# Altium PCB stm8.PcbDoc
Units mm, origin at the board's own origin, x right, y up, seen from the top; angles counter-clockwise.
Board outline 26 x 52.96 mm, 2 copper layers (Top Layer, Bottom Layer); 15 components, 22 nets, 75 pads, 10 vias.
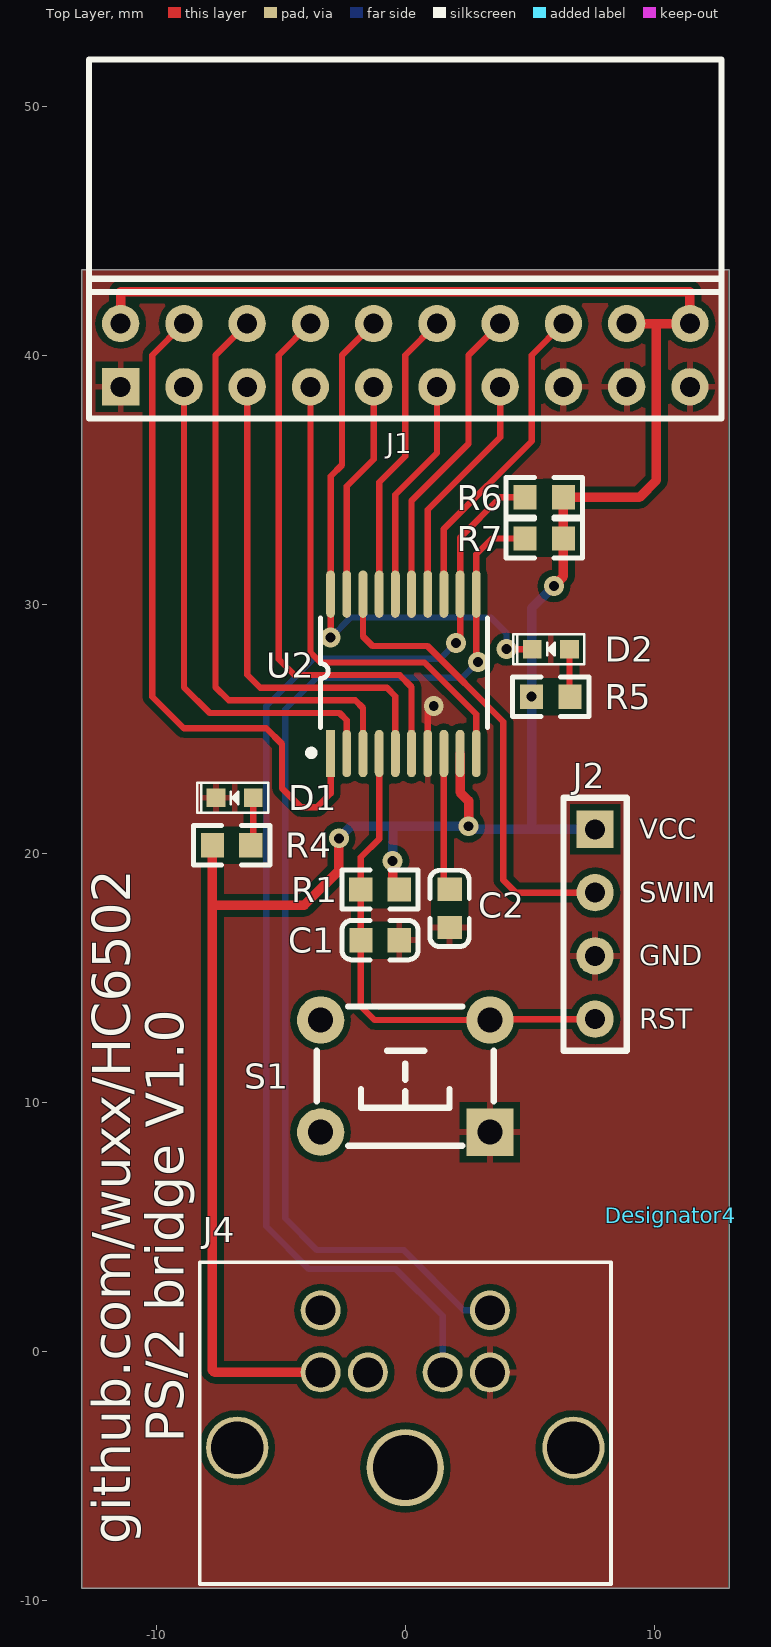
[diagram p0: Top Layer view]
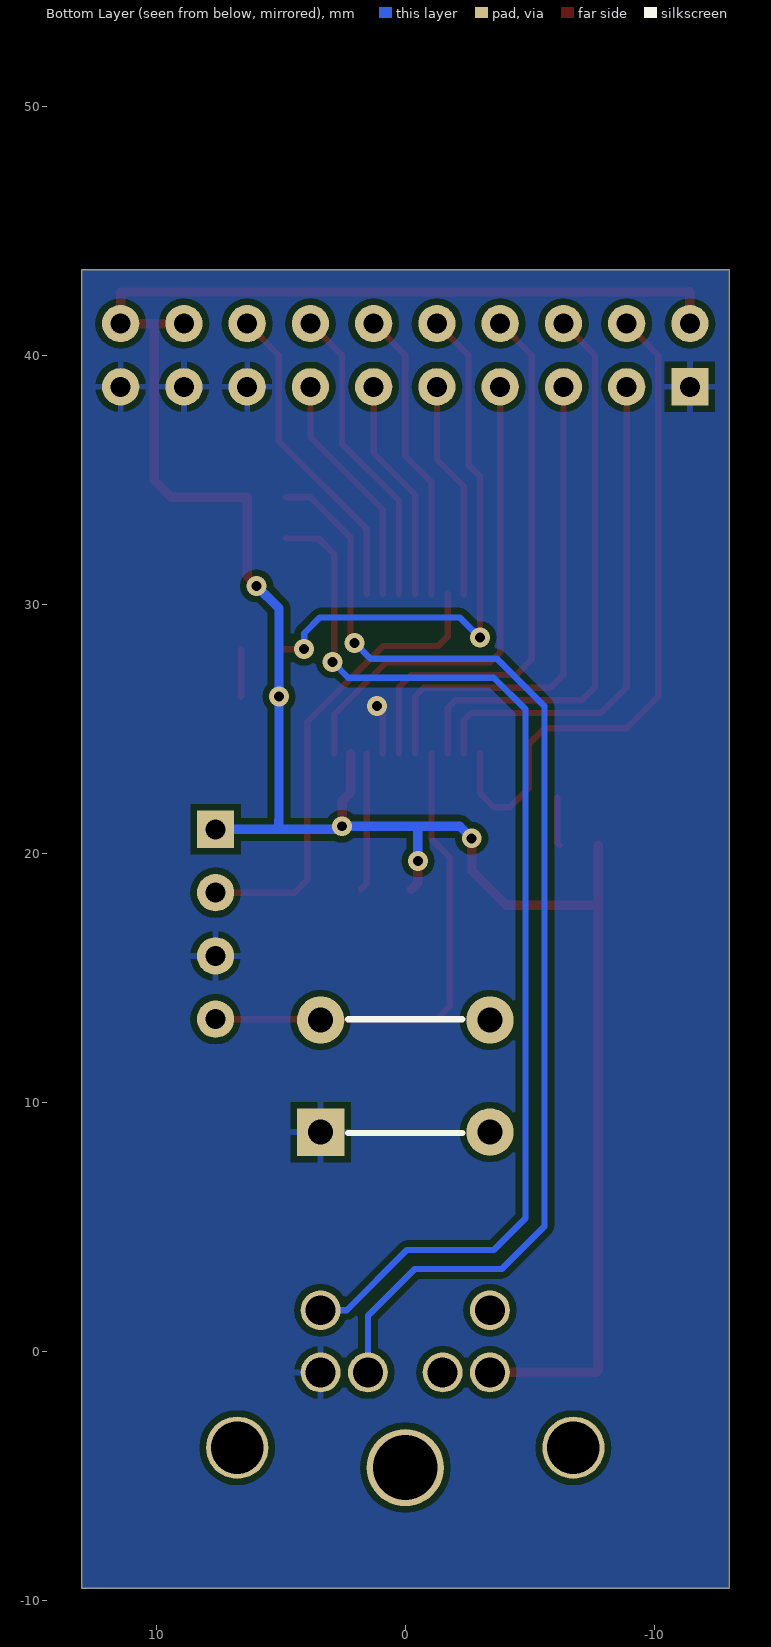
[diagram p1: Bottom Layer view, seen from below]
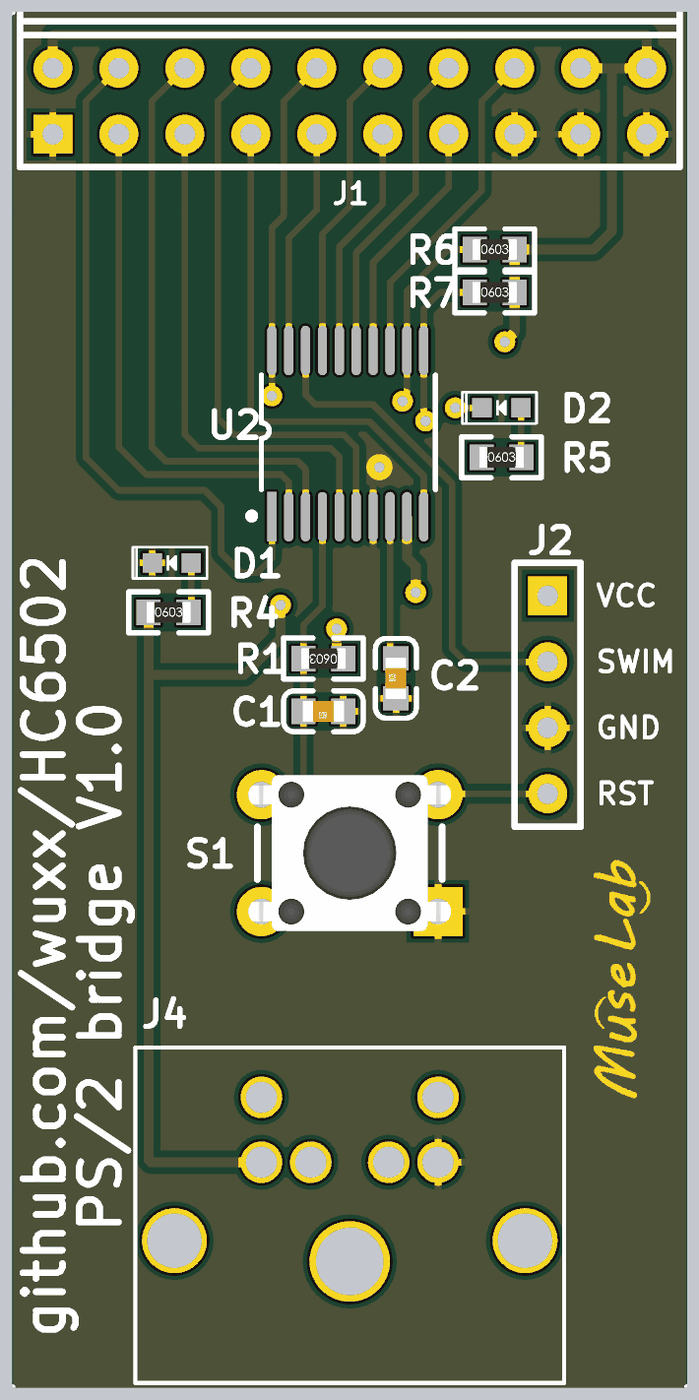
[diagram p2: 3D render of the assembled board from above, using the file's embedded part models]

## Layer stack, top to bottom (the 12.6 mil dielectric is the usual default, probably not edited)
Top Solder: solder mask 0.0102, Solder Resist, Dk 3.5
Top Layer: signal copper 0.0356
Dielectric 1: dielectric 0.32, FR-4, Dk 4.8
Bottom Layer: signal copper 0.0356
Bottom Solder: solder mask 0.0102, Solder Resist, Dk 3.5

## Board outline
-13,-9.525 -13,43.434 13,43.434 13,-9.525

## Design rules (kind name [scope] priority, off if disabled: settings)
Clearance [All] p1: gap=0.254 ignorepadtopadclearanceinfootprint=FALSE except(0: Arc-Hole Track-Hole SMDPad-Hole THPad-Hole Via-Hole Fill-Hole Poly-Hole Region-Hole Text-Hole)
DiffPairsRouting [All] p1: maxlimit=0.254 minlimit=0.254 mostfreqgap=0.254 toplayer_minwidth=0.152 toplayer_maxwidth=0.381 toplayer_prefwidth=0.381 bottomlayer_minwidth=0.152 bottomlayer_maxwidth=0.381 bottomlayer_prefwidth=0.381 maxuncoupledlength=12.7
PolygonConnect [All] p1: thpad.connectstyle=Relief thpad.reliefconductorwidth=0.254 thpad.reliefentries=4 thpad.polygonreliefangle="90 Angle" thpad.airgapwidth=0.254 smdpad.connectstyle=Relief smdpad.reliefconductorwidth=0.254 smdpad.reliefentries=4 smdpad.polygonreliefangle="90 Angle" smdpad.airgapwidth=0.254 via.connectstyle=Direct via.reliefconductorwidth=0.254 via.reliefentries=4 via.polygonreliefangle="90 Angle" via.airgapwidth=0.254
RoutingVias [All] p1: holewidth=0.4 width=0.8 viastyle="Through Hole" minholewidth=0.4 minwidth=0.8 maxholewidth=0.4 maxwidth=0.8
SolderMaskExpansion [All] p1: expansion=0.102
Width [All] p1: maxlimit=2.54 minlimit=0.152 preferedwidth=0.254
29 further rules are at their usual default settings.

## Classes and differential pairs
component class stm8: C1 C2 D1 D2 J1 J2 J4 R1 R4 R5 R6 R7 S1 U2

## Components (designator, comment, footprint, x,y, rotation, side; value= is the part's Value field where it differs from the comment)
C1 "Cap" 0603_C -0.254,16.51 r180 top value=100nF
C2 "Cap" 0603_C 1.778,17.018 r90 top value=1uF
D1 "LED0" 0603_LED -6.85,22.225 r180 top
D2 "LED0" 0603_LED 5.842,28.194 r180 top
Designator4 "Comment" LOGO 10.668,5.461 r90 top
J1 "IDC20" IDC20 0,40 r0 top
J2 "Header 4" HEADER_4x1 7.62,20.955 r270 top
J4 "PS2" PS2 0,-0.873 r180 top
R1 "Res2" 0603_R -0.254,18.542 r180 top value=1K
R4 "Res2" 0603_R -7.739,20.32 r0 top value=1K
R5 "Res2" 0603_R 5.08,26.289 r0 top value=1K
R6 "Res2" 0603_R 4.818,34.29 r0 top value=4.7K
R7 "Res2" 0603_R 4.818,32.639 r0 top value=4.7K
S1 "SW-PB" "TSW DIP-6*6*6" 0,11.049 r180 top
U2 "STM8S103F3P6" TSSOP20 -3,24.003 r90 top locked

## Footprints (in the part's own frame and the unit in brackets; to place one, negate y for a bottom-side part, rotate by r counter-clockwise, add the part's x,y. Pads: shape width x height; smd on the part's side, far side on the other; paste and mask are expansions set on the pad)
0603_C [mm]
  rect 0.93x0.98 smd: 1(-0.008,0) 2(1.532,0)
  silkscreen extent -0.77,-0.79 2.3,0.79, body extent -0.04,-0.4 1.56,0.4, height 0.3
0603_LED [mm]
  rect 0.75x0.75 smd: 1(-0.75,0) 2(0.75,0)
  silkscreen extent -1.35,-0.6 1.5,0.6
0603_R [mm]
  rect 0.93x0.98 smd: 1(-0.008,0) 2(1.532,0)
  silkscreen extent -0.77,-0.79 2.3,0.79, body extent -0.09,-0.4 1.61,0.4, height 0.56
HEADER_4x1 [mm]
  rect 1.5x1.5 hole 0.8: 1(0,0)
  round 1.5 hole 0.8: 2(2.54,0) 3(5.08,0) 4(7.62,0)
  silkscreen extent -1.27,-1.27 8.89,1.27
IDC20 [mm]
  rect 1.5x1.5 hole 0.8: 1(-11.43,-1.27)
  round 1.5 hole 0.8: 2(-11.43,1.27) 3(-8.89,-1.27) 4(-8.89,1.27) 5(-6.35,-1.27) 6(-6.35,1.27) 7(-3.81,-1.27) 8(-3.81,1.27) 9(-1.27,-1.27) 10(-1.27,1.27) 11(1.27,-1.27) 12(1.27,1.27) 13(3.81,-1.27) 14(3.81,1.27) 15(6.35,-1.27) 16(6.35,1.27) 17(8.89,-1.27) 18(8.89,1.27) 19(11.43,-1.27) 20(11.43,1.27)
  silkscreen extent -12.7,-2.54 12.7,11.87
LOGO [mm]
PS2 [mm]
  round 1.6 hole 1.2: 1(-1.5,-0.02) 2(1.5,-0.02) 3(-3.4,-0.02) 4(3.4,-0.02) 5(-3.4,-2.52) 6(3.4,-2.52)
  round 2.5 hole 2.1: 7(-6.75,3) 9(6.75,3)
  round 3.1 hole 2.6: 8(0,3.8)
  silkscreen extent -8.26,-4.44 8.25,8.48
TSSOP20 [mm] "20-pin, 4.40 mm body, 0.65 mm pitch"
  rect 1.9x0.356 smd: 1(0,0)
  oval 1.9x0.356 smd: 2(0,-0.65) 3(0,-1.3) 4(0,-1.95) 5(0,-2.6) 6(0,-3.25) 7(0,-3.9) 8(0,-4.55) 9(0,-5.2) 10(0,-5.85) 11(6.4,-5.85) 12(6.4,-5.2) 13(6.4,-4.55) 14(6.4,-3.9) 15(6.4,-3.25) 16(6.4,-2.6) 17(6.4,-1.95) 18(6.4,-1.3) 19(6.4,-0.65) 20(6.4,0)
  silkscreen extent -0.1,-6.3 5.45,0.9
"TSW DIP-6*6*6" [mm] "6*6*6mm"
  rect 1.9x1.9 hole 1: 1(-3.4,2.25)
  round 1.9 hole 1: 2(-3.4,-2.25) 3(3.4,-2.25) 4(3.4,2.25)
  silkscreen extent -3.56,-2.79 3.56,2.79, body extent -4.11,-3 4.11,3, height 5.95

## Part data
C1 C2: "Capacitor"
D1 D2: "Typical INFRARED GaAs LED"
J2: "Header, 4-Pin"
R1 R4 R5 R6 R7: "Resistor"
S1: "Switch"
U2: "ST 8-bit  Microcontroller"

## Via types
v1: diameter 0.8, hole 0.4, Top Layer to Bottom Layer, 10 vias

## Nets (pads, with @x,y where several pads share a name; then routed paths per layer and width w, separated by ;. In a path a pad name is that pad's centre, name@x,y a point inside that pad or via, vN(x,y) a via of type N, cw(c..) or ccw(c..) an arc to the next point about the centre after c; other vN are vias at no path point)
5V: J1.2 J1.18 J1.20 J2.1 J4.4 R1.1 R4.1 R5.1 R6.2 R7.2 U2.9 | length 100.9
  Top Layer w0.254: R5.1@5.072,26.17 v1(5.072,26.289)
  Top Layer w0.381: J1.2 -11.43,42.545 11.43,42.545 J1.20 10.033,41.27 ; R4.1 -7.747,17.907 ; J4.4 -7.656,-0.853 -7.747,-0.762 -7.747,17.907 ; v1(-2.667,20.599) -2.667,19.304 -4.064,17.907 -7.747,17.907 ; v1(-0.508,19.685) -0.508,18.804 R1.1 ; U2.9 2.2,22.438 2.54,22.098 v1(2.54,21.082) ; v1(5.969,30.734) 6.35,31.115 R7.2 R6.2 9.398,34.29 10.085,34.977 10.085,41.218 10.033,41.27 ; J1.18 10.033,41.27
  Bottom Layer w0.381: v1(-2.667,20.599) -2.184,21.082 -0.508,21.082 ; v1(-0.508,19.685) -0.508,21.082 ; v1(5.969,30.734) 5.072,29.837 v1(5.072,26.289) 5.072,21.328 5.08,21.32 5.08,20.955 ; J2.1 5.08,20.955 ; -0.508,21.082 v1(2.54,21.082) 2.667,20.955 5.08,20.955
GND: C1.1 C2.1 D1.2 J1.1 J1.15 J1.17 J1.19 J2.3 J4.3 S1.1 U2.7 | length 2
  Top Layer w0.254: U2.7 0.9,25.665 v1(1.143,25.908)
NetC2_2: C2.2 U2.8 | length 5.5
  Top Layer w0.254: U2.8 1.55,18.778 C2.2
NetD1_1: D1.1 R4.2 | length 1.9
  Top Layer w0.254: R4.2 -6.1,20.427 D1.1
NetD2_1: D2.1 R5.2 | length 1.9
  Top Layer w0.254: D2.1 6.592,26.309 R5.2
NRST: C1.2 J2.4 R1.2 S1.2 U2.4 | length 20.1
  Top Layer w0.254: U2.4 -1.05,20.572 -1.786,19.836 R1.2 -1.786,17.501 C1.2 -1.786,13.851 -1.234,13.299 S1.2 3.436,13.335 J2.4
PA1: J1.5 U2.5 | length 20.2
  Top Layer w0.254: J1.5 -6.35,27.164 -5.831,26.645 -0.737,26.645 -0.4,26.308 U2.5
PA2: J1.8 U2.6 | length 22.5
  Top Layer w0.254: J1.8 -5.08,40 -5.08,27.788 -4.445,27.153 -0.229,27.153 0.25,26.674 U2.6
PA3: J1.7 U2.10 | length 19.9
  Top Layer w0.254: J1.7 -3.81,28.067 -3.404,27.661 0.767,27.661 2.85,25.578 U2.10
PB4: J4.1 R6.1 U2.12 | length 48
  Top Layer w0.254: v1(2.032,28.448) 2.2,28.616 U2.12 2.2,32.68 3.81,34.29 R6.1
  Bottom Layer w0.254: J4.1 1.5,1.421 -0.381,3.302 -3.872,3.302 -5.588,5.018 -5.588,25.908 -3.683,27.813 1.397,27.813 v1(2.032,28.448)
PB5: J4.5 R7.1 U2.11 | length 45.3
  Top Layer w0.254: v1(2.921,27.686) 2.85,27.757 U2.11 2.85,32.004 3.485,32.639 R7.1
  Bottom Layer w0.254: v1(2.921,27.686) 2.286,27.051 -3.556,27.051 -4.826,25.781 -4.826,5.334 -3.556,4.064 -0.065,4.064 2.352,1.647 J4.5
PC3: J1.16 U2.13 | length 12.9
  Top Layer w0.254: U2.13 1.55,33.02 5.08,36.55 5.08,40 J1.16
PC4: J1.13 U2.14 | length 9.5
  Top Layer w0.254: U2.14 0.9,33.793 3.81,36.703 J1.13
PC5: J1.14 U2.15 | length 12.3
  Top Layer w0.254: U2.15 0.25,34.159 2.54,36.449 2.54,40 J1.14
PC6: J1.11 U2.16 | length 9
  Top Layer w0.254: U2.16 -0.4,34.398 1.27,36.068 J1.11
PC7: J1.12 U2.17 | length 11.8
  Top Layer w0.254: U2.17 -1.05,34.891 0,35.941 0,40 J1.12
PD1: J2.2 U2.18 | length 19
  Top Layer w0.254: U2.18 -1.7,28.702 -1.319,28.321 0.889,28.321 3.937,25.273 3.937,18.923 4.445,18.415 J2.2
PD2: J1.9 U2.19 | length 8.8
  Top Layer w0.254: U2.19 -2.35,34.734 -1.27,35.814 J1.9
PD3: D2.2 J1.10 U2.20 | length 22.7
  Top Layer w0.254: v1(-3,28.654) U2.20 -3,35.131 -2.54,35.591 -2.54,40 J1.10 ; v1(4.064,28.194) D2.2
  Bottom Layer w0.254: v1(-3,28.654) -2.19,29.464 3.429,29.464 4.064,28.829 v1(4.064,28.194)
PD4: J1.4 U2.1 | length 27.4
  Top Layer w0.254: J1.4 -10.16,40 -10.16,26.289 -8.89,25.019 -5.588,25.019 -4.953,24.384 -4.953,22.606 -4.191,21.844 -3.556,21.844 -3,22.4 U2.1
PD5: J1.3 U2.2 | length 20.5
  Top Layer w0.254: J1.3 -8.89,26.67 -7.849,25.629 -2.642,25.629 -2.35,25.337 U2.2
PD6: J1.6 U2.3 | length 23.2
  Top Layer w0.254: J1.6 -7.62,40 -7.62,26.67 -7.087,26.137 -2.007,26.137 -1.7,25.83 U2.3
pads on no net: J4.2 J4.6 J4.7 J4.8 J4.9 S1.3 S1.4

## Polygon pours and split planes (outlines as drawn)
GND on Top Layer "GND_L01_P004" (solid, remove dead copper, pour order 4): -12.954,-9.525 12.954,-9.525 12.954,43.434 -12.954,43.434
GND on Bottom Layer "GND_L02_P006" (solid, remove dead copper, pour order 6): -12.954,-9.525 12.954,-9.525 12.954,43.434 -12.954,43.434

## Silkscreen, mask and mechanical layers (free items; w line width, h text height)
Top Overlay:
  text "VCC" at 9.398,20.574 h0.81
  text "SWIM" at 9.398,18.034 h0.81
  text "GND" at 9.398,15.494 h0.81
  text "RST" at 9.398,12.954 h0.81
  text "PS/2 bridge V1.0" at -8.89,-3.683 h1.52 r90
  text "github.com/wuxx/HC6502" at -11.049,-7.747 h1.52 r90
Mechanical 1:
  the board outline again, w0.152

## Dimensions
-13,43.434 to -13,-9.525 on Top Overlay
-13,-9.525 to 13,-9.525 on Top Overlay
